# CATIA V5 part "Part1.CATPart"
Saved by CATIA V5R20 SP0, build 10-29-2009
Part number: 花瓶
Material "Bathroom Floor": density 2770 kg/m3, Young's modulus 6e+10 Pa, Poisson ratio 0.3
Material "Green": density 7860 kg/m3, Young's modulus 2e+11 Pa, Poisson ratio 0.266
Bounding box of the stored display mesh (mm): x -39.998 to 39.998, y -39.998 to 39.958, z -3.399 to 139.542
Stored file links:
  C:\Users\DELL\Desktop\王浩\Part1.CATPart
  E:\CATIA\win_b64\startup\materials\Catalog.CATMaterial
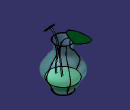
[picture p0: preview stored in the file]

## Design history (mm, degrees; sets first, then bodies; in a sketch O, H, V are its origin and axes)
Body1 (main body), material "Bathroom Floor"
  Plane1: type Offset, RefPlane xy-plane, Offset 20
  Plane2: type Offset, RefPlane Plane1, Offset 20
  Plane3: type Offset, RefPlane Plane2, Offset 20
  Plane4: type Offset, RefPlane Plane3, Offset 20
  Plane5: type Offset, RefPlane Plane4, Offset 20
  Sketch1 on xy-plane, origin (0, 0, 0), H (1, 0, 0), V (0, 1, 0)
    circle A1 centre (0, 0) radius 20
    point P1 (20, 0)
    radius A1 = 20
    coincidence: A1 P1, P1 H
  Sketch2 on Plane1, origin (0, 0, 20), H (1, 0, 0), V (0, 1, 0)
    circle A1 centre (0, 0) radius 30
    radius A1 = 30
  Sketch3 on Plane2, origin (0, 0, 40), H (1, 0, 0), V (0, 1, 0)
    circle A1 centre (0, 0) radius 40
    radius A1 = 40
  Sketch4 on Plane3, origin (0, 0, 60), H (1, 0, 0), V (0, 1, 0)
    circle A1 centre (0, 0) radius 30
    point P1 (30, 0)
    coincidence: A1 P1, P1 H
  Sketch5 on Plane4, origin (0, 0, 80), H (1, 0, 0), V (0, 1, 0)
    circle A1 centre (0, 0) radius 16
  Sketch6 on Plane5, origin (0, 0, 100), H (1, 0, 0), V (0, 1, 0)
    circle A1 centre (0, 0) radius 20
  Loft1: solid, Sections (Sketch1; Sketch2; Sketch3; Sketch4; Sketch5; Sketch6)
  Shell1: IntOffset 1, Face face of Loft1, ExtOffset 0
  Sketch7 on yz-plane, origin (0, 0, 0), H (0, 1, 0), V (0, 0, 1)
    spline S1 through (0, 0) (-6.0678, 50.4184) (-6.0678, 85.717) (31.7948, 117.343)
    spline S2 through (0, 0) (-16.2452, 26.2979) (-12.5555, 85.717) (-29.7815, 110.656)
    point P1 (0, 0)
    point P2 (0, 0)
    coincidence: P1 O, P2 O
  Plane6: type Normal, Curve Sketch7, RefPoint vertex of Sketch7
  Plane7: type Normal, Curve Sketch7
  Plane8: type Normal, Curve Sketch7, RefPoint vertex of Sketch7
  Sketch8 on Plane6, origin (0, 58.9059, 15.714), H (-1, 0, 0), V (0, -0.2578, 0.9662)
    circle A1 centre (0, 105.2985) radius 1.5
    point P1 (0, 105.2985)
    coincidence: P1 V
  Sketch9 on Plane8, origin (0, -72.1485, 53.2141), H (-1, 0, 0), V (0, 0.5936, 0.8048)
    circle A1 centre (0, 71.2804) radius 1.5
    point P1 (0, 71.2804)
    coincidence: P1 V
  Rib1: profile Sketch9, centre curve Sketch7
Body2, material "Green"
  Sketch10 on yz-plane, origin (0, 0, 0), H (0, 1, 0), V (0, 0, 1)
    axis line L1 (0, 118.7702) -> (0, -9.3558)
    point P1 (0, 118.7702)
    line L2 (0, 23.9845) -> (30.3166, 23.9845)
    point P3 (0, 23.9845)
    arc A1 centre (1.3387, 31.2302) radius 29.87 from (30.3166, 23.9845) to (0, 1.3902) cw
    point P6 (0, 1.3902)
    coincidence: P1 V, P3 L1, P6 L1
    vertical: L1 V
    horizontal: L2 H
  Shaft1: profile Sketch10, axis Sketch10.L1, angle 360
  Sketch11 on Plane8, origin (0, -72.1485, 53.2141), H (-1, 0, 0), V (0, 0.5936, 0.8048)
    spline S1 through (9.1126, 71.0822) (-2.4838, 80.0356) (-12.9773, 71.0822) (9.1126, 71.0822)
    point P1 (9.1126, 71.0822)
    point P2 (9.1126, 71.0822)
    coincidence: P1 P2
  Pad1: profile Sketch11, direction (0, 0.8048, -0.5936), length 1
  Sketch12 on Plane6, origin (0, 58.9059, 15.714), H (-1, 0, 0), V (0, -0.2578, 0.9662)
    spline S1 through (-6.9163, 98.6369) (-17.4324, 127.8181) (29.5918, 90.901) (-6.9163, 98.6369)
    point P1 (-6.9163, 98.6369)
    point P2 (-6.9163, 98.6369)
    coincidence: P1 P2
  Pad2: profile Sketch12, direction (0, 0.9662, 0.2578), length 1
